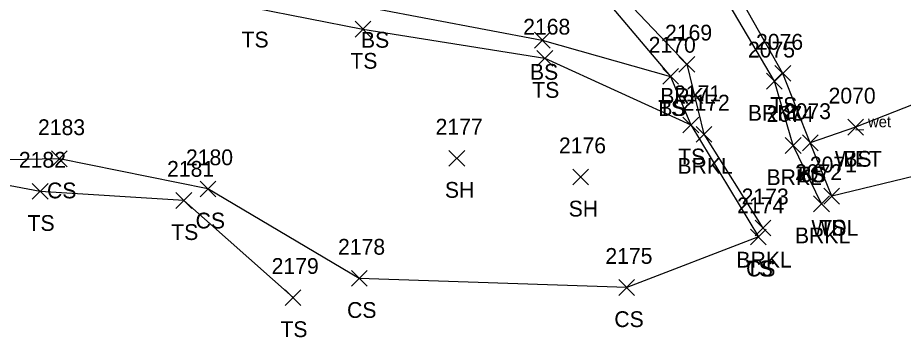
# Model space of a CAD drawing. Extents: x 1502194 to 1507887, y 142265 to 144150.
# Drawn here: x 1506728.1 to 1506840, y 143350.7 to 143391.2 of the extents above; entities that cross this region are included whole.
import ezdxf

# ---------------------------------------------------------------- set-up
doc = ezdxf.new("R2010")
doc.units = 0
for name, color, linetype in [('L_A', 7, 'Continuous'), ('L_I', 7, 'Continuous'), ('L_TIC', 7, 'Continuous'), ('LAWA', 7, 'Continuous'), ('LAWE', 7, 'Continuous'), ('LELB', 7, 'Continuous'), ('LWET', 7, 'Continuous')]:
    doc.layers.add(name, color=color, linetype=linetype)

msp = doc.modelspace()

# ---------------------------------------------------------------- linework, layer by layer
at = {"layer": 'L_TIC'}
for points in [[(1506770.75, 143388.69), (1506772.75, 143390.69)], [(1506772.75, 143388.69), (1506770.75, 143390.69)], [(1506793.42, 143387.3), (1506795.42, 143389.3)], [(1506795.42, 143387.3), (1506793.42, 143389.3)], [(1506793.74, 143385.01), (1506795.74, 143387.01)], [(1506795.74, 143385.01), (1506793.74, 143387.01)], [(1506811.68, 143384.26), (1506813.68, 143386.26)], [(1506813.68, 143384.26), (1506811.68, 143386.26)], [(1506809.64, 143382.72), (1506811.64, 143384.72)], [(1506811.64, 143382.72), (1506809.64, 143384.72)], [(1506809.64, 143382.72), (1506811.64, 143384.72)], [(1506811.64, 143382.72), (1506809.64, 143384.72)], [(1506823.82, 143383.1), (1506825.82, 143385.1)], [(1506825.82, 143383.1), (1506823.82, 143385.1)], [(1506822.75, 143382.11), (1506824.75, 143384.11)], [(1506824.75, 143382.11), (1506822.75, 143384.11)], [(1506812.18, 143376.58), (1506814.18, 143378.58)], [(1506814.18, 143376.58), (1506812.18, 143378.58)], [(1506812.18, 143376.58), (1506814.18, 143378.58)], [(1506814.18, 143376.58), (1506812.18, 143378.58)], [(1506833.02, 143376.29), (1506835.02, 143378.29)], [(1506835.02, 143376.29), (1506833.02, 143378.29)], [(1506813.85, 143375.4), (1506815.85, 143377.4)], [(1506815.85, 143375.4), (1506813.85, 143377.4)], [(1506825.12, 143373.97), (1506827.12, 143375.97)], [(1506827.12, 143373.97), (1506825.12, 143375.97)], [(1506827.29, 143374.32), (1506829.29, 143376.32)], [(1506829.29, 143374.32), (1506827.29, 143376.32)], [(1506827.29, 143374.32), (1506829.29, 143376.32)], [(1506829.29, 143374.32), (1506827.29, 143376.32)], [(1506732.38, 143372.29), (1506734.38, 143374.29)], [(1506734.38, 143372.29), (1506732.38, 143374.29)], [(1506782.62, 143372.36), (1506784.62, 143374.36)], [(1506784.62, 143372.36), (1506782.62, 143374.36)], [(1506798.27, 143369.99), (1506800.27, 143371.99)], [(1506800.27, 143369.99), (1506798.27, 143371.99)], [(1506729.95, 143368.17), (1506731.95, 143370.17)], [(1506731.95, 143368.17), (1506729.95, 143370.17)], [(1506751.16, 143368.48), (1506753.16, 143370.48)], [(1506753.16, 143368.48), (1506751.16, 143370.48)], [(1506748.11, 143367.02), (1506750.11, 143369.02)], [(1506750.11, 143367.02), (1506748.11, 143369.02)], [(1506830, 143367.57), (1506832, 143369.57)], [(1506832, 143367.57), (1506830, 143369.57)], [(1506830, 143367.57), (1506832, 143369.57)], [(1506832, 143367.57), (1506830, 143369.57)], [(1506828.7, 143366.6), (1506830.7, 143368.6)], [(1506830.7, 143366.6), (1506828.7, 143368.6)], [(1506821.31, 143363.53), (1506823.31, 143365.53)], [(1506823.31, 143363.53), (1506821.31, 143365.53)], [(1506820.73, 143362.41), (1506822.73, 143364.41)], [(1506822.73, 143362.41), (1506820.73, 143364.41)], [(1506820.73, 143362.41), (1506822.73, 143364.41)], [(1506822.73, 143362.41), (1506820.73, 143364.41)], [(1506770.29, 143357.16), (1506772.29, 143359.16)], [(1506772.29, 143357.16), (1506770.29, 143359.16)], [(1506804.08, 143356), (1506806.08, 143358)], [(1506806.08, 143356), (1506804.08, 143358)], [(1506761.91, 143354.73), (1506763.91, 143356.73)], [(1506763.91, 143354.73), (1506761.91, 143356.73)]]:
    msp.add_lwpolyline(points, dxfattribs=at)
at = {"layer": 'LAWA'}
msp.add_lwpolyline([(1506932.63, 143515.25), (1506892.28, 143496.29), (1506848.11, 143472.7), (1506850.82, 143464.05), (1506853.59, 143453.42), (1506870.03, 143452.38), (1506881.97, 143434.8), (1506885.44, 143414.92), (1506883.11, 143387.01), (1506858.52, 143375.25), (1506831, 143368.57)], dxfattribs=at)
at = {"layer": 'LAWE'}
msp.add_lwpolyline([(1506829.7, 143367.6), (1506826.12, 143374.97), (1506823.75, 143383.11), (1506813.52, 143400.48), (1506803.22, 143412.75), (1506800.83, 143416.93), (1506796.38, 143416.98), (1506789.68, 143424.84), (1506782.34, 143426.13), (1506780.5, 143431.34), (1506777.4, 143431.12), (1506774.14, 143428.63), (1506773, 143420.81), (1506785.56, 143413.5), (1506796.43, 143402.38), (1506812.68, 143385.26), (1506814.85, 143376.4), (1506822.31, 143364.53)], dxfattribs=at)
at = {"layer": 'LELB'}
for points in [[(1506853.59, 143453.42), (1506862.01, 143445.56), (1506870.5, 143431.63), (1506881.04, 143415.09), (1506868.07, 143393.64), (1506854.7, 143385.43), (1506834.02, 143377.29), (1506828.29, 143375.32)], [(1506831, 143368.57), (1506828.29, 143375.32), (1506824.82, 143384.1), (1506815.57, 143400.44), (1506805.68, 143411.3), (1506813.96, 143417.06), (1506815.4, 143427.32), (1506813.75, 143431.19), (1506802.31, 143428.76), (1506800.3, 143418.06), (1506796.71, 143418.56), (1506790.41, 143425.02), (1506782.75, 143426.35), (1506781.64, 143431.63), (1506776.99, 143440.27), (1506771.28, 143442.14), (1506769, 143436.63), (1506771.18, 143428.84), (1506771.51, 143422.43), (1506765.83, 143425.3), (1506750.65, 143429.58), (1506741.41, 143420.6), (1506730.3, 143416.13), (1506716.06, 143423.61)], [(1506821.73, 143363.41), (1506805.08, 143357), (1506771.29, 143358.16), (1506752.16, 143369.48), (1506733.38, 143373.29), (1506711.32, 143372.85), (1506683.88, 143374.9), (1506657.49, 143380.4), (1506618.98, 143397.77), (1506593.06, 143405.28), (1506569.34, 143407.78), (1506558.21, 143408.76), (1506558.16, 143410.47)], [(1506680.81, 143385.8), (1506700.49, 143392.33), (1506721.56, 143393.15), (1506724.7, 143404.46), (1506733.41, 143410.22), (1506745.22, 143408.74), (1506754.57, 143407.63), (1506773.81, 143399.34), (1506785.18, 143398.23), (1506783.59, 143408.91), (1506786.24, 143410.9), (1506795.32, 143401.84), (1506810.64, 143383.72), (1506813.18, 143377.58), (1506821.73, 143363.41)], [(1506733.41, 143410.22), (1506740.19, 143401.78), (1506760.23, 143398.98), (1506773.06, 143392.35), (1506794.42, 143388.3), (1506810.64, 143383.72)], [(1506733.41, 143410.22), (1506736.47, 143400.11), (1506758, 143392.38), (1506771.75, 143389.69), (1506794.74, 143386.01), (1506813.18, 143377.58)], [(1506762.91, 143355.73), (1506749.11, 143368.02), (1506730.95, 143369.17), (1506711.32, 143372.85)]]:
    msp.add_lwpolyline(points, dxfattribs=at)

# ---------------------------------------------------------------- texts
at = {"layer": 'L_A'}
for s, p in [('TS', (1506756.41, 143387.38)), ('BS', (1506771.5, 143387.35)), ('TS', (1506770.16, 143384.69)), ('BS', (1506792.86, 143383.3)), ('TS', (1506793.15, 143381.01)), ('BRKL', (1506809.33, 143380.26)), ('TS', (1506809.05, 143378.72)), ('BS', (1506809.08, 143378.72)), ('BRKL', (1506820.4, 143378.11)), ('TS', (1506823.23, 143379.1)), ('TS', (1506811.59, 143372.58)), ('TS', (1506811.59, 143372.58)), ('BRKL', (1506811.5, 143371.4)), ('WET', (1506831.4, 143372.29)), ('BS', (1506832.46, 143372.29)), ('TS', (1506826.69, 143370.32)), ('BS', (1506826.73, 143370.32)), ('BRKL', (1506822.76, 143369.97)), ('CS', (1506731.82, 143368.29)), ('SH', (1506782.11, 143368.36)), ('SH', (1506797.75, 143365.99)), ('TS', (1506729.36, 143364.17)), ('CS', (1506750.6, 143364.48)), ('WDL', (1506828.42, 143363.57)), ('TS', (1506829.41, 143363.57)), ('TS', (1506747.52, 143363.02)), ('BRKL', (1506826.35, 143362.6)), ('BRKL', (1506818.95, 143359.53)), ('TS', (1506820.14, 143358.41)), ('CS', (1506820.17, 143358.41)), ('CS', (1506769.74, 143353.16)), ('CS', (1506803.52, 143352)), ('TS', (1506761.32, 143350.73))]:
    msp.add_text(s, height=2, dxfattribs=at).set_placement(p)
at = {"layer": 'L_I'}
for s, p in [('2168', (1506792, 143389.01)), ('2169', (1506809.93, 143388.26)), ('2076', (1506821.43, 143387.1)), ('2170', (1506807.86, 143386.72)), ('2170', (1506807.86, 143386.72)), ('2075', (1506820.41, 143386.11)), ('2171', (1506811.06, 143380.58)), ('2171', (1506811.06, 143380.58)), ('2070', (1506830.6, 143380.29)), ('2070', (1506830.6, 143380.29)), ('2172', (1506812.16, 143379.4)), ('2073', (1506824.95, 143378.32)), ('2073', (1506824.95, 143378.32)), ('2074', (1506822.78, 143377.97)), ('2183', (1506730.68, 143376.29)), ('2177', (1506780.93, 143376.36)), ('2176', (1506796.52, 143373.99)), ('2180', (1506749.38, 143372.48)), ('2182', (1506728.26, 143372.17)), ('2071', (1506828.23, 143371.57)), ('2071', (1506828.23, 143371.57)), ('2181', (1506746.99, 143371.02)), ('2072', (1506826.36, 143370.6)), ('2173', (1506819.61, 143367.53)), ('2174', (1506819.04, 143366.41)), ('2174', (1506819.04, 143366.41)), ('2178', (1506768.6, 143361.16)), ('2175', (1506802.39, 143360)), ('2179', (1506760.21, 143358.73))]:
    msp.add_text(s, height=2, dxfattribs=at).set_placement(p)
at = {"layer": 'LWET'}
msp.add_text('_ wet', height=1.4, dxfattribs=at).set_placement((1506834.02, 143377.29))

doc.saveas('drawing.dxf')
